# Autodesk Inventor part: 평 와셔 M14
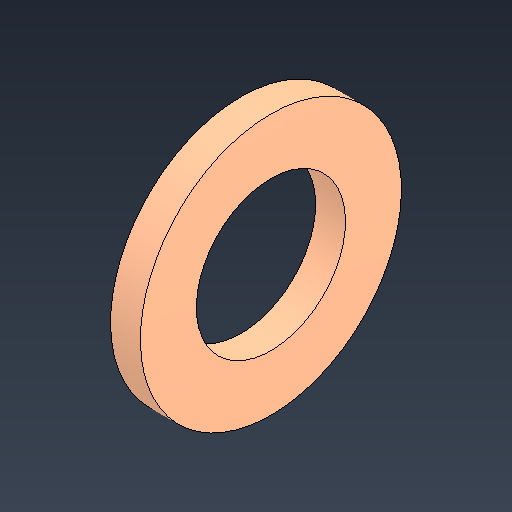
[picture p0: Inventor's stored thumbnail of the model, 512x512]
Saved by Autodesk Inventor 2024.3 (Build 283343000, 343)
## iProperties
Created: 2025-07
Part Number: 평 와셔 M14
Material: 강철, 연강
Description: 평면 와셔
Document SubType Name: Modeling
Designer: user
Density: 7.85 g/cm^3
Appearance: 기본값
Author: jhkim
Sending System: Autodesk Inventor 2026
Preprocessor: ST-DEVELOPER v20.1
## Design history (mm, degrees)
feature "Solid1"
node "솔리드1"
